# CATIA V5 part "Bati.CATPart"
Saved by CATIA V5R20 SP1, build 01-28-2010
Part number: Bati
Publications: "A", "K", "Droite.1", "Droite.2", "Droite.3", "Plan.3"
Bounding box of the stored display mesh (mm): x 0 to 0, y 0 to 20, z -100 to 150
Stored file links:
  C:\Users\Geoffray\Documents\Ifma\IAO\Exercice IAO\Catia\Bati.CATPart
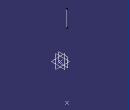
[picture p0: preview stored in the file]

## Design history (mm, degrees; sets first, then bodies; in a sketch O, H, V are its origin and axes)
Body1 (main body)
  Plane1 "Plan_ref": stored without definition
  Point1 "A": type OnPlane, Support Plane1, H 0, V 0, Direction (0, 1, 0)
  Plane2 "Plan_ref": stored without definition
  Point2 "K": type OnPlane, Support Plane2, H 20, V -100, Direction (0, 1, 0)
  Line1: type PtDir, RefPoint Point2, Direction xy-plane, Start 200, End 250
  Line2: type PtDir, RefPoint Point1, Direction yz-plane, Start -50, End 50
  Line3: type PtDir, RefPoint Point2, Direction yz-plane, Start -50, End 50
  Plane3: type Offset, RefPlane yz-plane, Offset 0
  Plane4: type Offset, RefPlane yz-plane, Offset 9, reversed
